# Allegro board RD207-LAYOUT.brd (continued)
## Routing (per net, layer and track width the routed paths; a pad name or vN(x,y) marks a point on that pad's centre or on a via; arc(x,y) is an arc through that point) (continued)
GND: length 396.6
  TOP w0.25: CN9.5 426.72,126.75 ; 426.72,126.75 427.32,126.15 427.63,125.83 ; 426.72,126.75 426.22,127.25 CN9.7 ; CN9.24 v1(415,131.25) ; CN9.32 419.8,133.25 419.33,133.72 v1(419.2,134.3) 419.2,134.95 419.5,135.25 CN9.40 ; v1(414.5,129.35) 415.25,129.35 416.15,130.25 CN9.20 ; v1(413.8,125.2) 414.66,125.46 417.45,128.25 CN9.12 ; CN9.39 426.75,135.25 v1(427.5,134.5) 426.25,133.25 CN9.31 ; v1(429.5,125.7) 426.95,128.25 CN9.11 ; CN9.50 419.5,137.75 419.33,137.92 v1(419.2,138.5) ; CN9.8 418.85,127.25 v1(418.2,126.6) 419.1,126.75 CN9.6 ; CN9.16 416.75,129.25 414.85,127.35 v1(413.8,127.35) ; v1(429.4,131.7) 428.95,131.25 CN9.23 ; v1(429.6,127.8) 429.09,128.11 427.95,129.25 CN9.15 ; CN9.19 429.1,130.25 v1(429.55,129.8)
  TOP w0.3: 175.5,72.25 178,72.25 ; 405.2,205.56 405.2,205.05 405.5,204.75 405.5,203.25 ; 186.5,74.29 186.5,75.76 ; 127.3,73 126.75,73 126.5,73.25 v1(126.5,75.25) 127,75.75 128.08,75.75 ; 81,88 81,86.75 80.75,86.5 IC32.2 ; 410.86,105.5 v1(409.6,105.5) ; 427.63,125.83 427.63,125.1 ; v1(409.45,147.78) 409.19,147.24 409.07,147.12 IC14.8 ; v1(409.45,147.78) IC14.9 ; v1(409.45,147.78) 408.71,148.51 408.1,148.51 ; 184,79.75 183.75,79.5 183.75,78.25 184,78 184,77 183.75,76.75 IC35.2 181.32,76.75 ; IC15.7 406.52,87.75 ; 141.7,83.5 142.25,83.5 142.5,83.25 142.5,81.75 141.75,81 140.49,81 ; 397.5,204.2 398.81,204.2 ; IC33.2 125.75,79.5 v1(125.25,80) ; 404.49,86 404.49,87.5 ; v1(399.55,142.7) 400.07,143.22 IC14.19 ; C121.2 88.55,81.95 88.5,82 88.5,82.5 ; 412.25,82.75 412.25,81.49 ; v1(130.5,83.5) 130.5,84.76 ; IC15.19 409.77,77.5 ; 403.1,140 402.24,140 ; 120.95,74 121.75,74 v1(122.5,73.25) ; 417.85,105.5 416.99,105.5 ; 83.5,85.51 v1(83.5,84.25) ; v1(128,88.25) 128,86 127.75,85.75 IC34.2 ; 405.5,203.25 408,203.25 ; 405.5,203.25 404.55,203.25 ; 404.3,208.25 404.7,208.25 405.2,207.75 405.2,205.94 ; IC15.6 407.18,87.25 ; 89.95,76.75 90.75,76.75 91.5,76 v1(91.5,74) 89.74,74 ; C126.2 v1(406.25,212.25) ; 186.64,97 187.5,97 ; C123.2 135.5,80.3 v1(135.5,79) ; C129.2 418.7,205.45 419.5,206.25 419.5,207 419,207.5 418.55,207.5 ; 109.7,70 110.5,70 v1(111.25,69.25) ; v1(141,79) 141,80.3 C124.2 ; 418.51,205 v1(417.25,205) ; 400.5,204.01 v1(400.5,202.75) ; 99.3,92.95 99.3,93.81 ; 168.4,75.8 169.55,75.8 v1(170,76.25) ; 419.5,202.5 422.19,202.5 ; 419.5,202.5 419.5,203.45 418.7,204.25 418.7,204.81 ; 419.5,202.5 418.55,202.5 ; v1(122.5,71) 120.49,71 ; 402.05,138.95 402.05,139.81 ; 110.75,67.25 109.24,67.25 ; 413.75,81.3 412.44,81.3 ; 410.75,81.3 412.06,81.3 ; 436.69,216.05 437.43,216.05 C114.2 ; 411.72,204.2 412.81,204.2 ; 410.51,85.99 410.51,86.75 ; 183.75,87 183.75,84.75 184,84.5 184,83.25 183.75,83 IC36.2 ; v1(416.25,211) 417.25,212 C107.2 ; 65.35,62 64.49,62 ; IC15.3 409.12,86.5 408.38,87.25 ; 130.5,78.51 v1(130.5,77.25) ; v1(137.5,82.25) 137.5,83 137,83.5 136.2,83.5 ; v1(90,81) 88.74,81 ; 64.3,63.05 64.3,62.19 ; 416.8,106.55 416.8,105.69 ; 105,74.24 v1(105,75.75) ; IC15.9 405.23,87.5 ; 78.9,68.8 77.69,68.8 ; 186.5,80.75 186.5,82.01 ; 81.64,97 83,97 ; IC15.8 405.88,87.38 ; 111.25,73.26 v1(111.25,71.75) ; 399.19,204.2 400.31,204.2 ; 427.3,126.13 426.71,126.72 ; 78.5,81 79.25,81 ; 79.25,81 79,80.75 ; 79.25,81 IC31.2 ; 83.5,80.01 v1(83.5,78.75) ; 89.45,83.5 88.3,83.5 ; 414.5,204.01 v1(414.5,202.75) ; v1(96.5,81) 95.24,81 ; 420.95,211.25 420.95,210.15 ; 405.01,205.75 v1(403.75,205.75) ; 414.31,204.2 413.19,204.2 ; 413,202.5 413,204.01 ; 165.5,76.45 v1(165.5,78) ; 419.5,212.2 418.02,212.2 ; 414.2,115.5 414.2,114.19 ; 410.69,85.4 411.75,85.4 ; 106.8,74.25 105.95,74.25 105.75,74.05 105.19,74.05 ; IC15.5 407.82,87.5 ; 151.5,97.64 151.5,98.51 ; 100.35,94 99.49,94 ; 107.3,74.25 108.75,74.25 ; 77.5,70.25 77.5,68.99 ; 404.31,85.4 403.25,85.4 ; 130.64,97 131.55,97 ; 399,202.75 399,204.01 ; IC15.4 408.48,87.25
  TOP w0.4: 401.31,211.86 v1(401.31,210.5) ; 417.6,107.5 417.5,107.5 ; 417.5,107.5 D10.A ; 417.5,107.5 418,107
  TOP w0.45: C52.2 410.86,105.5 ; C39.2 186.64,97 ; C97.2 151.5,97.64 ; C35.2 130.64,97 ; C25.2 81.64,97
  TOP w0.5: 410.93,103.5 v1(409.6,103.5) ; 404.31,85.4 IC15.10 404.49,86 ; 409.25,142 408.76,142.49 IC14.1 ; 418.55,207.5 IC23.2 ; IC21.2 404.3,208.25 ; 76.12,73.27 77.55,73.27 ; 149.43,94.5 148.29,94.5 ; 411.2,103.22 411.2,102.2 411,102 411,100.78 ; 181.09,101.9 181.09,99.06 180.59,98.56 ; IC28.2 89.95,76.75 ; 406,216.5 L17.2 L17.1 410,216.5 ; 426.75,217.75 PS7.2 ; IC18.2 136.2,83.5 ; 410.51,85.99 IC15.1 410.69,85.4 ; 420.31,140.44 419.6,140.44 419.2,140.04 v1(419.2,138.5) ; 133,97.5 L15.2 L15.1 136.75,97.5 ; 425.88,140.44 426.8,140.44 ; 187.42,94 188.5,94 ; 393.75,216.5 L16.1 L16.2 389.75,216.5 ; 131.32,94 133,94 ; IC2.2 410.6,111.25 ; 127.3,73 IC20.2 ; 75.65,73.48 75.65,74.65 ; 89.75,97.5 L14.1 L14.2 86,97.5 ; 81.58,94 82.5,94 ; IC30.2 165.5,76.45 ; IC22.2 404.55,203.25 ; IC19.2 141.7,83.5 ; 149.43,92.5 148.29,92.5 ; 146.57,94 147.71,94 ; 413.93,114 v1(412.7,114) ; 107.3,74.25 IC1.2 106.8,74.25 ; IC17.2 97.67,83.5 ; IC10.2 109.7,70 ; IC14.10 408.1,148.51 ; IC16.2 89.45,83.5 ; IC29.2 120.95,74 ; IC24.2 418.55,202.5
  TOP w0.6: CN9.60 420.31,140.44 ; CN9.59 425.88,140.44 ; CT2.5 124.59,97.91 ; 435,216.29 v1(435,217.5) ; 436.5,216.29 v1(436.5,217.5) ; CT1.5 75.59,96 ; CT3.5 181.09,101.9
  TOP w0.8: 418.51,205 C129.2 418.7,204.81 ; 436.69,216.05 C115.2 436.5,216.29 ; C143.2 83.5,80.01 ; 414.5,204.01 R124.2 414.31,204.2 ; C98.2 149.43,94.5 ; C38.2 187.42,94 ; 99.3,93.81 C85.2 99.49,94 ; 413.93,114 C48.2 414.2,114.19 ; C99.2 149.43,92.5 ; C50.2 111.25,73.26 ; C144.2 83.5,85.51 ; 105,74.24 C51.2 105.19,74.05 ; 400.5,204.01 C105.2 400.31,204.2 ; C125.2 128.08,75.75 ; 420.95,210.15 C128.2 ; 402.24,140 C117.2 402.05,139.81 ; 398.81,204.2 R115.1 ; R115.1 399.19,204.2 ; R115.1 399,204.01 ; C146.2 130.5,78.51 ; C127.2 405.2,205.56 ; C127.2 405.2,205.94 ; C127.2 405.01,205.75 ; C101.2 401.31,211.86 ; 413,204.01 C108.1 ; C108.1 413.19,204.2 ; C108.1 412.81,204.2 ; 140.49,81 C124.2 ; C24.2 81.58,94 ; 411.2,103.22 R24.1 410.93,103.5 ; 130.5,84.76 C147.2 ; 64.49,62 LED2.C 64.3,62.19 ; 418.02,212.2 C107.2 ; 416.8,105.69 C53.2 416.99,105.5 ; 77.5,68.99 R142.1 77.69,68.8 ; 412.25,81.49 C118.2 ; C118.2 412.06,81.3 ; C118.2 412.44,81.3 ; 75.65,73.48 PC7.3 76.12,73.27 ; C116.2 435,216.29 ; 95.24,81 C122.2 ; 109.24,67.25 C93.2 ; 186.5,82.01 C150.2 ; C37.2 131.32,94 ; C89.2 146.57,94 ; 120.49,71 C141.2 ; 186.5,75.76 C149.2 ; C140.2 89.74,74 ; C142.2 168.4,75.8 ; 88.74,81 C121.2
  TOP w1: PS6.2 152.75,98.72 151.5,98.72 ; 66.7,65 TP9.1 62.3,65 ; 148,94.5 148,97.75 148.97,98.72 151.5,98.72 ; 148,94.5 148.29,94.5 ; 148,94.5 148,94 ; 62.9,57.83 62.9,56.75 ; 439,217.5 v1(436.5,217.5) v1(435,217.5) 430.75,217.5 430.29,217.97 PS7.2 ; 151.5,98.51 151.5,98.72 ; 147.71,94 148,94 ; 148,94 148,92.5 ; 148,92.5 148.29,92.5 ; 148,92.5 148,87.06 ; CN8.2 411,100.78 ; 63.42,59 64.5,59
  TOP w1.2: C120.2 57.65,48 ; C120.2 59.25,50.75 ; C120.2 57.65,53.25 ; 62.9,42.9 PS2.7 62.9,46.1 ; 63.42,59 C23.2 62.9,57.83
  TOP w1.5: TP54.1 423.5,214.9 ; TP54.1 425.95,217 ; TP54.1 421.05,217 ; CN8.2 411,97.1
  TOP w1.7: TP52.1 148,87.06
  CONDUCTIVE2 w0.3: PS2.7 61.8,43.4 ; PS2.7 64,43.4 ; PS2.7 61.85,45.55 ; PS2.7 64,45.6 ; 153.25,98 PS6.2 155.75,97.93
  CONDUCTIVE2 w0.5: PS7.2 428.46,216.5 ; PS7.2 430.25,217.97 ; PS7.2 426.75,217.97
  BOTTOM w0.3: 431.45,129.85 430.3,129.85
  BOTTOM w1: 62.9,46.05 PS2.7 62.9,42.85
  vias: v1(15.5,24) v1(15.5,17) v1(28.5,24) v1(30.5,11) v1(40.5,24) v1(40.5,9) v1(52.5,11) v1(54.5,24) v1(58.5,30) v1(58.5,26) v1(58.5,9) v1(60.5,52) v1(60.5,49) v1(60.5,19) v1(63,56.5) v1(63.5,40) v1(63.5,31) v1(65,59) v1(66,52) v1(66.5,9) v1(69.5,63) v1(70.5,46) v1(70.5,35) v1(71.5,52) v1(72.5,12) v1(73.5,65.5) v1(73.5,61) v1(74.5,91) v1(74.5,86) v1(74.5,80) v1(75,54) v1(76.5,76.75) v1(77.5,73.25) v1(78.25,79) v1(78.5,46) v1(78.5,9) v1(79.25,60.25) v1(79.5,67) v1(79.7,55.73) v1(81,88.75) v1(83.5,19) v1(84,51.25) v1(85,69.5) v1(85.5,34) v1(86.25,53.5) v1(86.5,49) v1(86.5,9) v1(87.75,79.25) v1(89,66) v1(89.5,61.01) v1(91.5,50) v1(94.5,9) v1(95.5,54) v1(96.5,70) v1(96.5,66) v1(96.5,61) v1(97.5,76.25) v1(98.5,72.75) v1(98.75,44) v1(99.5,91) v1(99.5,30) v1(100.5,89) v1(101.5,85.5) v1(101.5,81) v1(102.5,54) v1(102.5,19) v1(102.5,9) v1(104.75,78.5) v1(105,69.5) v1(106.5,63) v1(106.75,65.75) v1(108.5,54) v1(108.5,9) v1(110.75,50) v1(111.5,78.5) v1(111.5,63) v1(114,55.75) v1(114.5,9) v1(114.75,51.25) v1(115.5,28) v1(116,59.75) v1(117,66.75) v1(117.25,43.75) v1(118.5,78.5) v1(118.5,19) v1(119,47.75) v1(121.5,9) v1(122.25,88) v1(122.25,84.75) v1(122.25,53.25) v1(122.75,42.75) v1(123,13.25) v1(123.25,66.75) v1(123.25,60.75) v1(123.25,38) v1(125.25,83.5) v1(126.5,69) v1(126.5,60.75) v1(126.5,53) v1(126.5,49) v1(127,43) v1(128.5,37.25) v1(128.5,32.5) v1(131.5,69) v1(131.75,88.25) v1(132.5,61) v1(132.5,53) v1(132.5,25) v1(132.75,37.25) v1(133,17.25) v1(133.25,41.75) v1(134.75,75.25) v1(137.25,70) v1(138.5,61) v1(138.5,53) v1(139.25,49) v1(139.75,75.25) v1(140.75,25) v1(141.95,38.5) v1(143.25,18.25) v1(144.25,25.75) v1(144.75,79) v1(145.5,74) v1(145.5,66.75) v1(145.5,61) v1(146.75,19) v1(147.5,81) v1(147.5,33) v1(148,53.25) v1(149.25,20.75) v1(149.5,16) v1(150.5,49) v1(150.5,42) v1(151.5,24) v1(152.25,81) v1(153.5,9) v1(154.5,66.75) v1(155.25,74) v1(155.25,61) v1(156.95,38.5) v1(157,81) v1(158.35,47) v1(158.75,53) v1(159.25,81) v1(162.5,66.75) v1(162.5,42) v1(162.5,32) v1(163,74.25) v1(163.5,61) v1(165.5,24) v1(167.5,9) v1(168.5,53) v1(169.5,67) v1(169.5,62) v1(169.5,49) v1(169.5,39) v1(170.5,15) v1(172.5,79) v1(173.5,75.5) v1(173.5,67) v1(176.25,70) v1(177.5,79) v1(177.5,77) v1(177.5,65.75) v1(177.5,51) v1(177.5,31) v1(177.75,59.25) v1(177.75,55.75) v1(178.5,40) v1(178.5,9) v1(179.5,92) v1(179.5,85.25) v1(180,75) v1(183.5,35) v1(184.25,65.75) v1(184.25,59.25) v1(184.5,53) v1(184.5,23) v1(184.75,90) v1(184.75,87.25) v1(184.75,80.5) v1(184.75,74.75) v1(184.75,70.75) v1(185.5,15) v1(189.5,29) v1(191.5,44) v1(193.5,9) v1(199.5,15) v1(200.5,37) v1(205.5,9) v1(208.5,29) v1(214.5,15) v1(219.5,9) v1(227.5,9) v1(235.5,15) v1(243.5,9) v1(253.5,15) v1(253.75,9) v1(277.75,9) v1(279.5,15) v1(286.5,9) v1(296.5,9) v1(306.5,9) v1(324.5,9) v1(339.5,10) v1(355.5,9) v1(369.5,10) v1(375.2,219.4) v1(375.5,207.5) v1(380.5,247) v1(384.5,186) v1(385.5,214) v1(385.5,117) v1(385.5,86) v1(385.5,81.75) v1(385.5,41) v1(385.5,26) v1(385.6,137.3) v1(386.5,66) v1(386.6,204.3) v1(387.5,161) v1(387.5,59) v1(389.25,217.25) v1(389.5,167) v1(389.5,48) v1(389.5,30) v1(390,145) v1(390,137.5) v1(390.5,198.75) v1(390.75,192.5) v1(391.25,177.25) v1(392.25,201.75) v1(393.7,214.5) v1(395.1,128.2) v1(396.25,163.5) v1(396.4,197) v1(396.4,176.7) v1(396.5,160.1) v1(397.5,137.5) v1(401.5,130.25) v1(402.25,155) v1(402.25,150.75) v1(402.25,134.25) v1(402.5,198) v1(402.5,187) v1(402.5,10) v1(404,138) v1(405.5,131.5) v1(405.75,134.25) v1(405.75,115.25) v1(405.95,216.7) v1(405.9,98.2) v1(406.5,88) v1(406.5,70) v1(406.5,46) v1(406.5,33) v1(408.75,101.25) v1(409.5,18) v1(409.75,163.5) v1(409.75,154) v1(409.75,134.25) v1(410,201.75) v1(410.15,140.9) v1(410.25,184) v1(410.5,168) v1(410.6,111) v1(411.5,60) v1(412.25,132.25) v1(412.5,187.5) v1(412.5,85) v1(412.75,152.25) v1(414,138.25) v1(415,134.5) v1(415.25,101.25) v1(415.5,45) v1(416.25,188.25) v1(416.25,155.5) v1(416.25,153) v1(420,147) v1(421,164) v1(421.25,144) v1(421.5,106) v1(422.5,85) v1(422.5,10) v1(425.25,152.5) v1(426.5,54) v1(426.5,27) v1(426.75,141.25) v1(428.25,155) v1(430,198) v1(430,145.5) v1(430,115) v1(433,10) v1(433.5,139.25) v1(433.75,149) v1(435.5,18) v1(438.5,112) v1(438.5,86) v1(438.5,45) v1(440,216) v1(440,198) v1(440,186) v1(440,167) v1(440,142) v1(440,117) v1(440,99) v1(440,81) v1(440,59) v1(440,33) v1(440,18) v1(441.25,162.25) v1(441.25,155) v1(441.5,212)
GND_5VAC: length 75.4
  TOP w0.3: 151.5,108.86 151.5,107.46
  TOP w0.45: C96.2 151.5,108.86
  TOP w0.5: 136.69,108.63 136.69,111.03 ; 151.5,107.46 151.5,107.25 ; 149.43,114.25 148.34,114.25 ; TP37.1 145.75,112.91 ; 145.75,112.91 144.59,112.91 ; 145.75,112.91 147.78,112.91 ; 149.43,112.75 148,112.75 ; R84.2 90.5,110.6 89.69,109.79 89.69,108.63 ; 149.49,115.86 148.36,115.86 ; v1(89,111.2) 90.22,111.2
  TOP w0.6: R99.2 v1(137.9,111.31) ; 97.82,112.8 v1(99,112.8)
  TOP w0.8: C94.2 149.43,114.25 ; R144.1 149.49,115.86 ; C88.2 144.59,112.91 ; 136.69,111.03 R99.2 ; 90.22,111.2 R84.2 ; C84.2 97.82,112.8 ; C95.2 149.43,112.75
  TOP w1: 151.5,107.25 151.25,107.25 148.75,109.75 v1(148.75,110.75) 148.07,111.43 148.07,112.91 ; PS6.5 153.58,107.21 153.5,107.25 151.75,107.25 ; v1(149.25,118.25) 148.07,117.07 148.07,115.86 ; 148.07,115.86 148.07,114.25 ; 148.07,115.86 148.36,115.86 ; 148.07,112.91 148.07,114.25 ; 148.07,112.91 147.78,112.91 ; 148.07,114.25 148.34,114.25
  TOP w1.5: IC9.4 136.69,108.63 ; 89.69,108.63 IC8.4
  CONDUCTIVE2 w1: 137.25,107.5 119.75,107.5 119.5,107.25 103.75,107.25
  CONDUCTIVE3 w0.3: 153.3,108 PS6.5 155.5,107.87
GND_5VDC: length 23.9
  TOP w0.3: 423.61,231 422.5,231 ; 410.19,227.55 410.19,230.12 ; 393.69,230.12 393.69,227.55
  TOP w0.45: C113.2 423.61,231
  TOP w0.5: 423.18,234.25 422.25,234.25 ; 423.18,232.5 422.25,232.5 ; 423.18,236 422.25,236 ; 409.92,230.31 v1(408.6,230.31) ; 393.42,230.31 v1(392.1,230.31) ; 418.08,231.91 v1(419.5,231.91) ; 401.57,231.91 v1(402.8,231.91)
  TOP w0.6: 427.25,226.8 PS7.5 429.75,226.87
  TOP w0.8: C103.2 401.57,231.91 ; C112.2 423.18,232.5 ; C111.2 423.18,234.25 ; 410.19,230.12 R129.2 409.92,230.31 ; R145.1 423.18,236 ; 393.42,230.31 R114.2 393.69,230.12 ; C106.2 418.08,231.91
  TOP w1.5: 393.69,227.55 IC12.4 ; IC13.4 410.19,227.55
  CONDUCTIVE2 w0.5: 427.3,226.75 PS7.5 429.5,226.62
  vias: v1(421.75,235.25) v1(421.75,233.5) v1(421.75,231.75) v1(422.25,226.25) v1(424,226.25) v1(425.75,226.25)
GND_24V: length 154.6
  TOP w0.3: 39.7,71.05 39.7,70.19 ; 38.65,70 39.51,70 ; 34.3,71.05 34.3,70.19 ; 39.7,68.95 39.7,69.81 ; 36.3,37 36.3,35.69 ; 36.3,34.45 36.3,35.31 ; 34.3,68.9 34.3,69.81 ; 38,35.5 36.49,35.5 ; 35.35,70 34.49,70
  TOP w0.4: 68.27,76.8 67.01,76.8 Q7.S ; 68.73,76.8 v1(70,76.8)
  TOP w0.5: PS2.1 45.85,44.5 ; PS2.1 47.6,46.1 ; PS2.1 47.6,42.8 ; 62.42,83 v1(60.83,83) ; 111.42,84 v1(109.5,84) ; 168.43,84 v1(166.5,84)
  TOP w0.6: CN1.2 34.5,65 ; CN1.2 34.5,62 ; CN1.2 36,63.5
  TOP w0.8: 68.27,76.8 R143.1 68.73,76.8 ; 36.3,35.69 LED1.C ; LED1.C 36.49,35.5 ; LED1.C 36.3,35.31 ; 34.3,70.19 C19.2 ; C19.2 34.3,69.81 ; C19.2 34.49,70 ; 39.7,69.81 R12.2 ; R12.2 39.7,70.19 ; R12.2 39.51,70 ; C12.2 168.43,84 ; C1.2 62.42,83 ; C8.2 111.42,84
  TOP w1: C22.2 40.1,37.75 ; C22.2 40.1,33.25 ; C22.2 38.5,35.5 ; TP8.1 47.5,55.15 ; TP8.1 49.7,57 ; TP8.1 45.3,57 ; TP8.1 47.5,58.85 ; TP5.1 38.8,63 ; TP5.1 43.2,63 ; TP5.1 41,61.15 ; TP5.1 41,64.85 ; C21.2 38.75,32.9 ; C21.2 36.5,34 ; C21.2 34.5,32.9
  TOP w1.2: v1(375.6,108.3) C70.2 375.6,114.4 374.31,115.69 PS4.2 ; PS5.2 374.31,35.19 375.6,33.9 C78.2 v1(375.6,27.6) ; v1(375.6,186.6) C62.2 375.6,193.4 374.31,194.69 PS3.2 ; C120.1 53.35,53.75 ; C120.1 53.35,47.75 ; C120.1 51.5,50.75
  TOP w1.5: C20.2 43.05,50.75 ; ZD1.A v1(37.8,39.5) ; ZD1.A 35.55,42 ; ZD1.A 35.55,37.5 ; 40.75,53.75 40.75,47.5
  CONDUCTIVE2 w0.3: PS2.1 46.6,45.5 ; PS2.1 48.6,43.5 ; PS2.1 48.6,45.5 ; PS2.1 46.55,43.45 ; CN1.2 33.5,62.5 ; CN1.2 35.5,62.5 ; CN1.2 35.5,64.5 ; CN1.2 33.5,64.5
  CONDUCTIVE3 w0.3: PS2.1 48.7,45.6 ; PS2.1 48.55,43.55 ; PS2.1 46.5,43.4 ; PS2.1 46.5,45.6 ; CN1.2 33.5,62.5 ; CN1.2 35.5,64.5 ; CN1.2 33.5,64.5 ; CN1.2 35.5,62.5
  CONDUCTIVE3 w0.5: PS4.2 374.31,118.11 374.7,118.5 ; PS4.2 374.31,115.89 374.7,115.5 ; PS4.2 375.75,117 ; 374.7,194.5 374.31,194.89 PS3.2 ; PS5.2 374.31,37.61 374.6,37.9 ; PS5.2 375.75,36.5 ; PS5.2 374.31,35.39 374.6,35.1 ; PS3.2 374.31,197.11 374.7,197.5 ; PS3.2 375.75,196
  BOTTOM w1: PS2.1 47.6,46.55 ; PS2.1 47.6,42.45 ; PS2.1 45.55,44.5
  vias: v1(38,42) v1(38,36.5) v1(38.4,34.4) v1(39,43.5) v1(39,40.5) v1(39,38) v1(44.5,57)
/DO1_BI: length 70.1
  TOP w0.25: CN9.42 419.55,135.75 v1(419.15,136.15)
  TOP w0.3: R138.1 404,93.45 v1(404,136) ; IC15.2 409.77,86.67 409.7,86.75 409.7,87.56
  TOP w0.8: 409.7,87.56 R138.1
  BOTTOM w0.3: v1(404,136) 418,136 v1(419.15,136.15)
/MAINRLY_24V: length 62.1
  TOP w0.5: 62.35,85.28 62.35,89.2 RLY1.8 ; 59.5,84.65 59.5,82.47 R139.1 ; RLY2.8 108.75,87.25 110,86 111.16,86 ; 62.08,85 59.85,85 ; 168.07,86 167.25,86 165.75,87.5 RLY3.8 ; 64.2,76 63,76 59.4,79.6 59.4,81.47
  TOP w0.8: 168.07,86 D3.A ; 64.2,76 Q7.D ; 62.08,85 D1.A 62.35,85.28 ; R139.1 59.4,81.47 ; D2.A 111.16,86
  TOP w1.7: 59.85,85 TP50.1 59.5,84.65
  BOTTOM w1.5: RLY2.8 108.75,92.75 ; RLY2.8 110.75,94.8 ; RLY2.8 106.75,94.8 ; RLY1.8 59.75,89.5 ; RLY1.8 59.75,94 ; RLY1.8 57.75,91.8 ; RLY1.8 62,91.8 ; RLY3.8 163.45,91.8 ; RLY3.8 165.75,90 ; RLY3.8 165.75,94.1
/PWM1A_BI: length 37.2
  TOP w0.25: 428.5,132.2 428.05,131.75 CN9.25
  TOP w0.3: v1(430.3,139.5) 430.3,134 428.5,132.2 ; 412.76,141 v1(411.55,141) 409.32,143.22 IC14.2
  TOP w0.8: 412.76,141 R132.1
  BOTTOM w0.3: v1(430.3,139.5) 413.05,139.5 v1(411.55,141)
/PWM1B_BI: length 24
  TOP w0.25: CN9.26 418.45,131.75 418.4,131.8
  TOP w0.3: 418.4,131.8 416.6,133.6 v1(416.6,141) ; IC14.3 410.18,143.88 v1(411.55,142.5) 412.76,142.5
  TOP w0.8: 412.76,142.5 R133.1
  BOTTOM w0.3: v1(411.55,142.5) 413.05,141 v1(416.6,141)
/PWM2A_BI: length 37.7
  TOP w0.25: CN9.27 427.65,132.25 427.98,132.57
  TOP w0.3: 427.98,132.57 429.6,134.2 429.6,138.6 429.3,138.9 v1(429.3,142.6) ; IC14.4 411.02,144.53 v1(411.55,144) 412.76,144
  TOP w0.8: 412.76,144 R134.1
  BOTTOM w0.3: v1(429.3,142.6) 412.95,142.6 v1(411.55,144)
/PWM2B_BI: length 25.7
  TOP w0.25: 417.6,133.6 418.95,132.25 CN9.28
  TOP w0.3: IC14.5 410.89,145.18 410.99,145.27 v1(411.55,145.5) 412.76,145.5 ; v1(416.6,143.9) 417.6,142.9 417.6,133.6
  TOP w0.8: 412.76,145.5 R135.1
  BOTTOM w0.3: v1(416.6,143.9) 413.15,143.9 v1(411.55,145.5)
/PWM3A_BI: length 38.8
  TOP w0.25: CN9.29 427.25,132.75 427.75,133.25
  TOP w0.3: 427.75,133.25 428.9,134.4 428.9,138.4 428,139.3 v1(428,145.5) ; 412.76,147 v1(411.55,147) 410.38,145.82 IC14.6
  TOP w0.8: 412.76,147 R136.1
  BOTTOM w0.3: v1(428,145.5) 413.05,145.5 v1(411.55,147)
/PWM3B_BI: length 29.6
  TOP w0.25: CN9.30 419.35,132.75 418.2,133.9
  TOP w0.3: 418.2,133.9 418.2,146.41 v1(418.1,147) ; 412.76,148.5 v1(411.55,148.5) 409.52,146.47 IC14.7
  TOP w0.8: 412.76,148.5 R137.1
  BOTTOM w0.3: v1(418.1,147) 413.05,147 v1(411.55,148.5)
/PWM_U_A: length 122.3
  TOP w0.3: 395.77,142 397.25,142 399.12,143.88 IC14.18 ; TP44.1 393.5,144 393.5,193.09 393.43,193.46 393.21,193.79 389,198 389,215 379.5,224.5 379.5,246.3 379,246.8 378.19,246.8
  TOP w0.5: 377.73,246.8 377,246.8 376.53,247.27 376.12,247.27
  TOP w0.6: PC1.3 376.12,247.27
  TOP w0.8: 377.73,246.8 R35.2 378.19,246.8
  TOP w1.7: 395.77,142 TP44.1
/PWM_U_B: length 99.8
  TOP w0.3: IC14.17 398.23,144.53 v1(397.75,145) 395.77,145 ; v1(392.4,145) 392.7,145.52 392.7,193.3 388.49,197.51 388.27,197.84 388.2,198.21 388.2,214.7 379.6,223.3 378.19,223.3
  TOP w0.5: 376.12,223.77 376.7,223.77 377.17,223.3 377.73,223.3
  TOP w0.6: PC2.3 376.12,223.77
  TOP w0.8: 377.73,223.3 R40.2 378.19,223.3
  TOP w1.7: TP45.1 395.77,145
  BOTTOM w0.3: v1(397.75,145) v1(392.4,145)
/PWM_V_A: length 47.3
  TOP w0.3: IC14.16 399.32,145.18 397.75,146.75 v1(397.75,148) 395.77,148 ; 379.69,165.3 389.5,165.3 390.6,164.2 v1(390.6,148)
  TOP w0.5: PC3.3 378.2,165.77 378.67,165.3 379.23,165.3
  TOP w0.8: 379.69,165.3 R48.2 379.23,165.3
  TOP w1.7: TP46.1 395.77,148
  BOTTOM w0.3: v1(397.75,148) v1(390.6,148)
/PWM_V_B: length 41.8
  TOP w0.3: v1(385,151) 385,142 384.3,141.3 379.69,141.3 ; 395.77,151 v1(397.75,151) 398.85,149.9 398.85,147 400.02,145.82 IC14.15
  TOP w0.5: 379.23,141.3 377.97,141.3 377.5,141.77 376.12,141.77
  TOP w0.6: PC4.3 376.12,141.77
  TOP w0.8: 379.69,141.3 R53.2 379.23,141.3
  TOP w1.7: TP47.1 395.77,151
  BOTTOM w0.3: v1(397.75,151) v1(385,151)
/PWM_W_A: length 104.9
  TOP w0.3: v1(386.6,154) 387,152.87 387,84.8 385.5,83.3 379.69,83.3 ; 395.77,154 v1(397.75,154) 399.6,152.15 399.6,147.3 400.43,146.47 IC14.14
  TOP w0.5: 379.35,83.3 378.87,83.3 378.4,83.77 PC5.3
  TOP w0.8: 379.35,83.3 R61.2 379.69,83.3
  TOP w1.7: 395.77,154 TP48.1
  BOTTOM w0.3: v1(397.75,154) v1(386.6,154)
/PWM_W_B: length 131.5
  TOP w0.3: IC14.13 400.82,147.12 400.45,147.5 400.45,154.3 v1(397.75,157) 395.77,157 ; v1(388.6,157) 388.6,64.4 383.5,59.3 379.69,59.3
  TOP w0.5: R66.2 379.03,59.77 376.12,59.77
  TOP w0.6: PC6.3 376.12,59.77
  TOP w0.8: R66.2 379.69,59.3
  TOP w1.7: TP49.1 395.77,157
  BOTTOM w0.3: v1(397.75,157) v1(388.6,157)
AC_L_IN_W: length 107.4
  TOP w1: RLY3.5 163.75,116.8 ; RLY3.5 167.75,116.8 ; RLY3.5 165.75,118.75 ; 171.25,116.8 RLY3.4 173.25,118.75 ; R9.2 168.5,127 ; R9.2 173.5,127 ; R9.2 171,129.5 ; R9.2 171,124.5
  CONDUCTIVE2 w1: RLY3.5 165.75,118.75 ; RLY3.5 167.75,116.8 ; RLY3.5 163.75,116.8 ; R9.2 171,129.25 ; R9.2 171,124.75 ; R9.2 173.25,127 ; R9.2 168.5,127 ; 171.25,116.8 RLY3.4 173.25,118.75
  CONDUCTIVE3 w1: 173.25,118.75 RLY3.4 171.25,116.8 ; R9.2 173.5,127 ; R9.2 171,129.5 ; R9.2 168.5,127 ; R9.2 171,124.5 ; RLY3.5 163.75,116.8 ; RLY3.5 165.75,118.75 ; RLY3.5 167.75,116.8
  CONDUCTIVE3 w1.5: 143.51,260.47 L2.6 ; L2.6 140.18,262.89 ; L2.6 140.18,257.18 ; PS1.3 11.5,137.7 ; PS1.3 13.8,140 ; PS1.3 11.5,142.3 ; PS1.3 9.2,140
  BOTTOM w1: RLY3.5 163.75,116.8 ; RLY3.5 165.75,119 ; RLY3.5 168,116.8 ; 171.25,116.8 RLY3.4 173.25,119
  BOTTOM w1.5: R9.2 171,124.5 ; R9.2 171,129.5 ; R9.2 173.5,127 ; R9.2 168.5,127 ; 140.18,257.97 L2.6 ; L2.6 140.18,262.5 ; L2.6 142.68,260.47 ; L2.6 137.68,260.47
AC_N_IN: length 106.9
  TOP w1: R6.2 113.25,128.5 ; R6.2 108.25,128.5 ; R6.2 110.75,131 ; R6.2 110.75,126 ; 114.25,119.8 RLY2.4 116.25,122 ; L2.4 177.42,247.73 ; L2.4 175.17,245.48 ; L2.4 175.17,249.98 ; RLY2.5 108.75,121.75 ; RLY2.5 106.75,119.8 ; RLY2.5 110.75,119.8
  CONDUCTIVE2 w1: R6.2 110.75,131 ; R6.2 108.25,128.5 ; R6.2 110.75,126 ; R6.2 113,128.5 ; 114.25,119.8 RLY2.4 116.25,121.75 ; RLY2.5 106.75,119.8 ; RLY2.5 108.75,121.75 ; RLY2.5 110.75,119.8
  CONDUCTIVE2 w1.5: L2.4 175.17,250.13 ; L2.4 177.57,247.73 ; L2.4 175.17,245.33
  CONDUCTIVE3 w1: RLY2.5 108.75,121.75 ; RLY2.5 110.75,119.8 ; RLY2.5 106.75,119.8 ; 110.75,126.5 R6.2 108.75,128.5 ; 116.25,121.75 RLY2.4 114.25,119.8
  CONDUCTIVE3 w1.5: PS1.2 33.8,140 ; PS1.2 31.5,142.3 ; PS1.2 31.5,137.7 ; PS1.2 29.2,140 ; L2.4 177.57,247.73 ; L2.4 175.17,245.33 ; L2.4 172.77,247.73 ; L2.4 175.17,250.13
  BOTTOM w1: R6.2 110.75,131 ; R6.2 110.75,126 ; R6.2 113.25,128.5 ; R6.2 108.25,128.5 ; RLY2.5 108.75,122 ; RLY2.5 106.75,119.8 ; RLY2.5 110.75,119.8 ; 116.25,122 RLY2.4 114.25,119.8
AC_U: length 166.9
  TOP w0.3: 76.5,135.25 90.51,135.25
  TOP w0.8: 90.51,135.25 R75.1
  TOP w1: R1.1 72.25,129.5 ; R1.1 72.25,124.5 ; R1.1 74.75,127 ; R1.1 69.75,127 ; RLY1.6 59.75,109.75 ; RLY1.6 57.75,111.8 ; RLY1.6 61.75,111.8 ; RLY1.3 67.25,109.75 ; RLY1.3 69.25,111.8 ; RLY1.3 65.25,111.8 ; TP1.1 71.5,138 ; TP1.1 71.5,142 ; TP1.1 73.75,140 ; TP1.1 69.25,140
  TOP w1.5: C7.1 140.75,190.25 ; C7.1 138.5,188 ; C7.1 143,188 ; C7.1 140.75,185.75 ; C6.1 93.75,151.75 ; C6.1 96,154 ; C6.1 93.75,156.25 ; C6.1 91.5,154
  CONDUCTIVE2 w1: RLY1.3 69.25,111.8 ; RLY1.3 65.25,111.8 ; RLY1.3 67.25,109.75 ; R1.1 72.25,129.5 ; R1.1 74.75,127 ; R1.1 72.25,124.5 ; R1.1 69.75,127 ; RLY1.6 57.75,111.8 ; RLY1.6 61.75,111.8 ; RLY1.6 59.75,109.75
  CONDUCTIVE2 w1.5: C7.1 140.75,190.15 ; C7.1 140.75,185.85 ; C7.1 138.6,188 ; C7.1 142.9,188 ; C6.1 91.6,154 ; C6.1 93.75,156.15 ; C6.1 95.9,154 ; C6.1 93.75,151.85
  CONDUCTIVE3 w1: RLY1.6 59.75,109.75 ; RLY1.6 61.75,111.8 ; RLY1.6 57.75,111.8 ; C6.1 91.85,154 ; C6.1 93.75,155.9 ; C6.1 93.75,152.1 ; C6.1 95.65,154 ; R1.1 69.75,127 ; R1.1 74.75,127 ; R1.1 72.25,129.5 ; R1.1 72.25,124.5 ; RLY1.3 67.25,109.75 ; RLY1.3 69.25,111.8 ; RLY1.3 65.25,111.8
  CONDUCTIVE3 w1.5: C7.1 140.75,190.15 ; C7.1 138.6,188 ; C7.1 140.75,185.85 ; C7.1 142.9,188
  BOTTOM w1: R1.1 74.75,127 ; R1.1 72.25,124.5 ; R1.1 72.25,129.5 ; R1.1 69.75,127
  BOTTOM w1.5: C7.1 137.9,188 ; C7.1 143,188 ; C7.1 140.75,190.85 ; C7.1 140.75,185.15 ; 96.6,154 C6.1 93.75,151.15
  vias: v1(73,109.5) v1(73.5,113) v1(73.5,111) v1(74.5,114) v1(74.5,112) v1(74.5,109.5) v1(75.5,113) v1(75.5,111) v1(76,109.5)
AC_V: length 198.2
  TOP w0.3: 89.19,120.75 89.19,121.59 88.89,121.89 88.89,122.7 ; v1(89,127) 88.89,126 88.89,124.97 ; 137.69,119.53 137.69,121.4 138.68,122.39 139.7,122.39 ; 140.19,120.66 140.19,121.4 139.89,121.7 139.89,122.2 ; 88.89,124.7 88.89,123.08 ; v1(139.89,125.6) 139.89,124.08 ; v1(140.25,131) 140.25,133.25 138,135.5 136.52,135.5 ; 88.7,122.89 87.39,122.89 86.69,122.19 86.69,119.53 ; 139.89,122.58 139.89,123.7
  TOP w0.45: R101.1 137.69,119.53 ; R86.1 86.69,119.53
  TOP w0.6: L11.2 140.19,120.66 ; L10.2 89.19,120.75
  TOP w0.8: 88.89,122.7 C86.2 ; C86.2 88.89,123.08 ; C86.2 88.7,122.89 ; 139.89,124.08 R95.1 139.89,123.7 ; 139.7,122.39 C91.2 ; C91.2 139.89,122.2 ; C91.2 139.89,122.58 ; 88.89,124.97 R80.1 88.89,124.7
  TOP w1: RLY2.6 106.75,114.8 ; RLY2.6 108.75,112.75 ; RLY2.6 110.75,114.8 ; R6.1 120.25,126 ; R6.1 122.75,128.5 ; R6.1 120.25,131 ; R6.1 117.75,128.5 ; RLY2.3 114.25,114.8 ; RLY2.3 116.25,112.75 ; RLY2.3 118.25,114.8 ; TP2.1 131.25,140.5
  TOP w1.5: 133.5,154 C6.2 131.25,151.75 ; C9.1 138.5,154 ; C9.1 140.75,151.75 ; C9.1 143,154
  TOP w1.7: 136.52,135.5 TP2.1
  CONDUCTIVE2 w0.3: v1(139.89,125.6) 141.85,125.6 142.25,126 155.75,126 156,126.25 156,129 155.25,129.75 141.5,129.75 v1(140.25,131) ; v1(89,127) 95.25,127 95.5,127.25 95.5,135 95.25,135.25 91,135.25 90.25,134.5 v1(90.25,128.75)
  CONDUCTIVE2 w1: RLY2.6 110.75,114.8 ; RLY2.6 108.75,113 ; RLY2.6 106.75,114.8 ; RLY2.3 116.25,113 ; RLY2.3 118.25,114.8 ; RLY2.3 114.25,114.8
  CONDUCTIVE3 w0.3: 113,132.25 93.75,132.25 v1(90.25,128.75)
  BOTTOM w1: R6.1 122.75,128.5 ; R6.1 120.25,126 ; R6.1 117.75,128.5 ; R6.1 120.25,131
  BOTTOM w1.5: C9.1 140.75,151.15 ; C9.1 137.9,154 ; C9.1 143.6,154 ; C9.1 140.75,156.1 ; C6.2 134.1,154 ; C6.2 131.25,156.1 ; C6.2 131.25,151.15 ; C6.2 128.4,154
  vias: v1(121.25,116) v1(121.25,114) v1(122.25,117) v1(122.25,115) v1(123,131) v1(123,129) v1(123,127) v1(123.25,116) v1(123.25,114) v1(124,130) v1(124,128) v1(124,126) v1(124.25,117) v1(124.25,115) v1(125,131) v1(125,129) v1(125,127) v1(125.25,116) v1(125.25,114)
AC_W: length 132.6
  TOP w0.3: R87.1 161.95,135 177.5,135
  TOP w1: RLY3.6 163.5,111.8 ; RLY3.6 165.75,109.5 ; RLY3.6 168,111.8 ; RLY3.3 173.25,109.5 ; RLY3.3 175.5,111.8 ; RLY3.3 171,111.8 ; 188.44,116.5 185,116.5
  TOP w1.5: 180.5,188 C7.2 178.25,185.75 ; C9.2 176,154 ; C9.2 180.5,154 ; C9.2 178.25,156.25 ; C9.2 178.25,151.75 ; R9.1 180.5,129.5 ; R9.1 180.5,124.5 ; R9.1 178,127 ; R9.1 183,127
  TOP w1.7: TP3.1 188.44,116.5
  CONDUCTIVE2 w1: RLY3.3 171.5,111.8 ; RLY3.3 175,111.8 ; RLY3.3 173.25,110 ; RLY3.6 164,111.8 ; RLY3.6 165.75,110 ; RLY3.6 167.5,111.8
  CONDUCTIVE3 w1: RLY3.6 165.75,110 ; RLY3.6 164,111.8 ; RLY3.6 167.5,111.8 ; RLY3.3 175,111.8 ; RLY3.3 171.5,111.8 ; RLY3.3 173.25,110
  BOTTOM w1: RLY3.6 168,111.8 ; RLY3.6 163.5,111.8 ; RLY3.6 165.75,109.55 ; RLY3.3 173.25,109.5 ; RLY3.3 175.5,111.8 ; RLY3.3 171,111.8
  BOTTOM w1.5: C9.2 178.25,156.85 ; C9.2 181.1,154 ; C9.2 178.25,151.15 ; C9.2 175.4,154 ; C7.2 175.4,188 ; C7.2 178.25,190.85 ; C7.2 178.25,185.15 ; C7.2 181.1,188 ; R9.1 180.5,129.5 ; R9.1 180.5,124.5 ; R9.1 183,127 ; R9.1 178,127
  vias: v1(176.5,110.5) v1(177.5,111.5) v1(177.5,109.5) v1(178.5,110.5) v1(179.5,111.5) v1(179.5,109.5) v1(180.5,110.5) v1(181.5,111.5) v1(181.5,109.5) v1(187.5,128.5) v1(187.5,126.5) v1(187.5,124.5) v1(188.5,127.5) v1(188.5,125.5) v1(188.5,123.5) v1(189.5,128.5) v1(189.5,126.5) v1(189.5,124.5)
AD0: length 490.1
  TOP w0.25: CN9.9 426.6,127.75 428.5,125.85 v1(428.5,122.6)
  TOP w0.3: TP31.1 85.5,87 v1(85.5,84.45) 87.05,84.45 ; v1(399,122.5) 399,26.8 387.7,15.5 288,15.5 282,21.5 150.65,21.5 107.65,64.5 104.75,64.5 95.75,73.5 95.75,74.5 91.5,78.75 v1(91.5,82.55) 89.95,82.55
  TOP w0.5: IC16.4 87.05,84.45 ; IC16.1 89.95,82.55
  BOTTOM w0.3: v1(399,122.5) 427.5,122.5 v1(428.5,122.6) ; v1(85.5,84.45) 89.6,84.45 v1(91.5,82.55)
AD1: length 440.1
  TOP w0.25: v1(409.5,125) 410.5,124 414,124 417.75,127.75 CN9.10
  TOP w0.3: 133.8,84.45 134.3,84.45 134.75,84 134.75,82.8 135,82.55 135.7,82.55 ; v1(137.25,72) 137.25,79.75 135.95,81.05 135.95,82.38 ; 133.75,87.48 133.75,85.75 133.55,85.55 133.55,84.62 ; v1(391.5,125) 391.5,28.4 384.6,21.5 291,21.5 285,27.5 188.29,27.5 175.9,39.89 175.9,66.85 v1(173.5,69.25)
  TOP w0.5: 133.8,84.45 IC18.4 133.55,84.62 ; 135.95,82.38 IC18.1 135.7,82.55
  TOP w1.7: 133.75,87.48 TP34.1
  BOTTOM w0.3: v1(137.25,72) 140,69.25 v1(173.5,69.25) ; v1(409.5,125) v1(391.5,125)
AD2: length 130.7
  TOP w0.25: 430.2,126.8 429.15,126.8 427.2,128.75 CN9.13
  TOP w0.3: 406.45,207.45 406.45,207.75 405,209.2 404.3,209.2 ; TP38.1 402.5,210.25 v1(402.5,209.25) 403.25,209.2 403.8,209.2 ; v1(431.8,148.7) 431.8,127.9 430.7,126.8 430.2,126.8 ; v1(411.5,154) 412,154.5 412,184.5 393.8,202.7 v1(393.8,208.3)
  TOP w0.5: IC21.4 406.45,207.45 ; 404.3,209.2 IC21.1 403.8,209.2
  BOTTOM w0.3: v1(411.5,154) 426.5,154 v1(431.8,148.7) ; v1(402.5,209.25) 398.25,209.25 398,209.5 395,209.5 v1(393.8,208.3)
AD3: length 105.4
  TOP w0.25: 413.15,126.33 414.62,126.33 417.05,128.75 CN9.14
  TOP w0.3: 418.55,208.45 419.3,208.45 420.7,207.05 420.7,206.6 ; 418.05,208.45 417.3,208.45 v1(416.25,209.5) 417,210.25 418.48,210.25 ; 413.15,126.33 411.75,126.33 410.95,127.12 410.95,133.2 415.45,137.7 415.45,151.35 414.5,152.3 414.5,196.75 v1(416.25,198.5)
  TOP w0.5: IC23.4 420.7,206.6 ; 418.05,208.45 IC23.1 418.55,208.45
  TOP w1.7: 418.48,210.25 TP41.1
  BOTTOM w0.3: v1(416.25,198.5) v1(416.25,209.5)
AD4: length 505.8
  TOP w0.25: v1(430.8,128.8) 429.2,128.8 428.25,129.75 CN9.17
  TOP w0.3: v1(394,120) 394,27.8 385.7,19.5 290,19.5 284,25.5 187.75,25.5 173.5,39.75 v1(173.5,64.5) ; IC31.3 IC31.4 81.95,79.2 81.75,79 v1(81.75,77.75) 81.75,75.52
  TOP w1.7: 81.75,75.52 TP13.1
  BOTTOM w0.3: v1(394,120) 429.75,120 430.8,121.05 v1(430.8,128.8) ; v1(81.75,77.75) 81.75,75.75 93,64.5 v1(173.5,64.5)
AD5: length 456.3
  TOP w0.25: CN9.18 416.45,129.75 415.1,128.4 414.3,128.4
  TOP w0.3: 124.75,77.52 124.75,78.75 124.85,78.85 IC33.3 IC33.4 ; v1(401.5,128.5) 401.5,26.3 388.7,13.5 287,13.5 281,19.5 148.5,19.5 v1(124.75,43.25) ; 124.75,76.98 v1(124.75,50.5) ; 414.3,128.4 v1(412.9,128.4)
  TOP w1.7: 124.75,77.52 TP14.1 124.75,76.98
  BOTTOM w0.3: v1(401.5,128.5) 412,128.5 412.1,128.4 v1(412.9,128.4) ; v1(124.75,50.5) v1(124.75,43.25)
AD6: length 433.6
  TOP w0.25: CN9.21 430.07,130.75 v1(430.8,130.9)
  TOP w0.3: 181.98,72.25 180,72.25 179.25,71.5 171.95,71.5 171.2,70.75 171.2,39.5 187.2,23.5 283,23.5 289,17.5 386.6,17.5 396.5,27.4 v1(396.5,117.5) ; 182.25,72.52 182.25,75.75 182.6,76.1 IC35.3 IC35.4
  TOP w1.7: 181.98,72.25 TP15.1 182.25,72.52
  BOTTOM w0.3: v1(430.8,130.9) 432.1,130.9 432.75,130.25 432.75,119.5 430.75,117.5 v1(396.5,117.5)
AD7: length 43.4
  TOP w0.25: v1(413.5,130.3) 415.4,130.3 415.85,130.75 CN9.22
  TOP w0.3: v1(406.9,130.3) 406.9,117.35 412.05,112.2 413.05,112.2 ; 415.45,110.3 414.95,110.3 414.5,110.75 414.5,112 414.3,112.2 413.55,112.2
  TOP w0.5: 418.65,111.5 417.45,111.5 416.25,110.3 IC2.4 415.45,110.3 ; 413.05,112.2 IC2.1 413.55,112.2
  TOP w1.7: 418.65,111.5 TP10.1
  BOTTOM w0.3: v1(413.5,130.3) v1(406.9,130.3)
FG: length 235.8
  TOP w1: C13.2 56,312.5 ; C13.2 54,311 ; C13.2 58,311 ; C15.2 25,304 ; C15.2 27,305.5 ; C15.2 28.5,304 ; C18.2 156,312.8 ; C18.2 157.8,311 ; C18.2 154.2,311 ; C14.2 80,312.8 ; C14.2 78.2,311 ; C14.2 81.8,311 ; C16.2 129.8,311 ; C16.2 126.2,311 ; C16.2 128,312.8 ; C17.2 101.8,311 ; C17.2 100,312.8 ; C17.2 98.2,311
  TOP w1.5: TB4.2 13,314.4 ; TB4.2 9,311.4 ; TB4.2 13,308.4 ; TB4.2 17.75,311.4 ; TB4.1 13,305.6 ; TB4.1 17.75,302.6 ; TB4.1 9,302.6
  CONDUCTIVE2 w1: C18.2 156,312.7 ; C18.2 157.7,311 ; C18.2 154.3,311 ; C16.2 128,312.7 ; C16.2 129.7,311 ; C16.2 126.3,311 ; C15.2 25.3,304 ; C15.2 28.7,304 ; C15.2 27,305.7 ; C13.2 54.3,311 ; C13.2 57.7,311 ; C13.2 56,312.7 ; C14.2 80,312.7 ; C14.2 78.3,311 ; C14.2 81.7,311 ; C17.2 98.3,311 ; C17.2 100,312.7 ; C17.2 101.7,311
  CONDUCTIVE2 w1.5: TB4.2 13,314.4 ; TB4.2 8.3,311.4 ; TB4.2 17.75,311.4 ; TB4.2 13,308.4 ; TB4.1 8.3,302.6 ; TB4.1 13,305.6 ; TB4.1 17.75,302.6
  CONDUCTIVE3 w1: C18.2 157.7,311 ; C18.2 154.3,311 ; C18.2 156,312.7 ; C16.2 126.3,311 ; C16.2 129.7,311 ; C16.2 128,312.7 ; C14.2 78.3,311 ; C14.2 80,312.7 ; C14.2 81.7,311 ; C17.2 98.3,311 ; C17.2 101.7,311 ; C17.2 100,312.7 ; C15.2 27,305.7 ; C15.2 28.7,304 ; C15.2 25.3,304 ; C13.2 56,312.7 ; C13.2 54.3,311 ; C13.2 57.7,311
  CONDUCTIVE3 w1.5: TB4.2 13,308.4 ; TB4.2 17.75,311.4 ; TB4.2 13,314.4 ; TB4.2 8.4,311.4 ; TB4.1 8.3,302.6 ; TB4.1 17.75,302.6 ; TB4.1 13,305.6
  BOTTOM w1: C18.2 157.8,311 ; C18.2 156,312.8 ; C18.2 154.2,311 ; C15.2 28.8,304 ; C15.2 27,305.8 ; C15.2 25.2,304 ; C16.2 126.2,311 ; C16.2 128,312.8 ; C16.2 129.8,311 ; C13.2 57.8,311 ; C13.2 54.2,311 ; C13.2 56,312.8 ; C14.2 81.8,311 ; C14.2 80,312.8 ; C14.2 78.2,311 ; C17.2 100,312.8 ; C17.2 98.2,311 ; C17.2 101.8,311
  BOTTOM w1.5: TB4.1 8.3,302.6 ; TB4.1 13,305.6 ; TB4.1 17.75,302.6 ; TB4.2 13,314.4 ; TB4.2 8.3,311.4 ; TB4.2 13,308.4 ; TB4.2 17.75,311.4
GATE_U_A: length 3.6
  BOTTOM w1: Q1.G 352.23,250.15
GATE_U_B: length 3.6
  BOTTOM w1: Q2.G 352.23,226.15
GATE_V_A: length 3.6
  BOTTOM w1: Q3.G 352.23,168.15
GATE_V_B: length 3.6
  BOTTOM w1: Q4.G 352.23,144.15
GATE_W_A: length 3.5
  BOTTOM w1: Q5.G 352.23,86.05
GATE_W_B: length 3.6
  BOTTOM w1: Q6.G 352.23,62.15
IU: length 11.1
  TOP w0.3: 78,91.99 78,93.25 78.14,93.39 78.14,101.95
  TOP w0.6: CT1.7 78.14,101.95
  TOP w0.8: 78,91.99 R23.1
IV: length 10.6
  TOP w0.3: 127.14,101.95 127.14,93.44 R25.1
  TOP w0.6: 127.14,101.95 CT2.7
IW: length 13.4
  TOP w0.3: 182.75,89.99 182.75,98.05 183.63,98.94 183.63,101.95
  TOP w0.6: CT3.7 183.63,101.95
  TOP w0.8: 182.75,89.99 R26.2
SIG193: length 232.3
  TOP w1: 80.16,299 R2.1 78.16,297 ; ZNR3.2 49.25,239.35 ; ZNR3.2 51.25,241.35 ; ZNR3.2 49.25,243.35 ; R8.2 49.66,233 ; R8.2 49.66,237 ; R8.2 51.66,235 ; C14.1 80,299.8 ; C14.1 81.8,301 ; C14.1 78.2,301 ; L1.3 67.05,236.65 ; L1.3 64.8,238.9 ; L1.3 64.8,234.4 ; L1.3 62.55,236.65 ; C10.1 49.75,229.5 ; C10.1 52.25,227 ; C10.1 49.75,224.5 ; C2.2 83.75,291 ; C2.2 86.25,288.5 ; C2.2 86.25,293.5 ; ZNR1.1 76.75,279.35 ; ZNR1.1 74.75,281.35 ; ZNR1.1 74.75,277.6 ; F2.2 49,253.9 ; F2.2 50.9,252 ; F2.2 49,250.1
  CONDUCTIVE2 w1: C10.1 51.02,225.73 ; C10.1 48.48,228.27 ; C10.1 51.02,228.27 ; C10.1 48.48,225.73 ; R8.2 51.07,233.59 ; R8.2 48.25,236.41 ; R8.2 51.07,236.41 ; R8.2 48.25,233.59 ; F2.2 47.73,253.27 ; F2.2 47.73,250.73 ; F2.2 50.27,253.27 ; F2.2 50.27,250.73 ; R2.1 80.16,299 ; R2.1 75.9,299 ; R2.1 78.16,301 ; R2.1 78.16,297 ; C14.1 82.7,301 ; C14.1 80,299.8 ; C14.1 78.3,301 ; C2.2 86.25,292.8 ; C2.2 86.25,289.2 ; C2.2 84,291 ; C2.2 88.05,291 ; ZNR3.2 50.52,240.08 ; ZNR3.2 47.98,240.08 ; ZNR3.2 50.52,242.62 ; ZNR3.2 47.98,242.62 ; ZNR1.1 72.95,279.35 ; ZNR1.1 76.55,279.35 ; ZNR1.1 74.75,277.55 ; ZNR1.1 74.75,281.15
  CONDUCTIVE2 w1.5: L1.3 62.4,236.65 ; L1.3 64.8,234.25 ; L1.3 67.2,236.65 ; L1.3 64.8,239.05
  CONDUCTIVE3 w1: R8.2 51.66,235 ; R8.2 49.66,237 ; R8.2 49.66,233 ; ZNR3.2 49.25,239.55 ; ZNR3.2 49.25,243.15 ; ZNR3.2 51.05,241.35 ; C10.1 49.75,228.8 ; C10.1 49.75,225.2 ; C10.1 51.55,227 ; F2.2 50.8,252 ; F2.2 49,250.2 ; F2.2 49,253.8 ; R2.1 78.16,301 ; R2.1 76.16,299 ; R2.1 78.16,297 ; R2.1 80.16,299 ; 78.3,301 C14.1 81.7,301 ; C2.2 86.25,292.8 ; C2.2 86.25,289.2 ; C2.2 88.05,291 ; C2.2 84.45,291 ; 76.75,279.35 ZNR1.1 74.75,281.96
  CONDUCTIVE3 w1.5: 64.8,234.25 L1.3 62.4,236.65
  BOTTOM w1: R2.1 76.16,299 ; R2.1 78.16,301 ; R2.1 80.16,299 ; R2.1 78.16,297 ; R8.2 51.66,235 ; R8.2 49.66,237 ; R8.2 49.66,233 ; ZNR3.2 51.25,241.35 ; ZNR3.2 49.25,239.35 ; ZNR3.2 49.25,243.35 ; C2.2 86.25,288.5 ; C2.2 86.25,293.5 ; C2.2 88.4,291 ; C2.2 83.75,291 ; F2.2 50.9,252 ; F2.2 49,250.1 ; F2.2 49,253.9 ; 81.8,301 C14.1 78.2,301 ; 52.25,227 C10.1 49.75,229.5 ; 74.75,281.35 ZNR1.1 76.75,279.35
  BOTTOM w1.5: L1.3 62.3,236.65 ; L1.3 64.8,239.15 ; L1.3 64.8,234.15 ; L1.3 67.3,236.65
SOURCE_U: length 54.6
  TOP w0.3: 355.3,206.05 355.3,205.19 ; 355.3,203.95 355.3,204.81 ; 356.35,205 355.49,205
  TOP w0.5: 360.57,210.63 361.06,210.63 361.9,209.8 362.38,209.8 ; 362.5,210.07 v1(362.5,211.91) 360.83,211.91 ; 352.5,207.93 v1(352.5,206.5)
  TOP w0.6: IC4.3 360.57,210.63 ; IC4.4 360.83,211.91
  TOP w0.8: 362.5,210.07 C65.2 362.38,209.8 ; R45.1 352.5,207.93 ; 355.3,204.81 C64.2 ; C64.2 355.3,205.19 ; C64.2 355.49,205
  TOP w1: v1(356,202.2) C63.2 358.25,199.4
  TOP w1.2: PS3.5 366.1,196.59 366.1,198.3
  CONDUCTIVE2 w0.5: 366.3,194.5 366.69,194.89 PS3.5 ; 366.3,197.5 366.69,197.11 PS3.5 ; PS3.5 365.05,196
  CONDUCTIVE2 w1.5: Q2.S 354.53,233.45 ; Q2.S 352.23,235.75 ; Q2.S 352.23,231.15 ; 354.53,257.45 Q1.S 352.23,255.25
  CONDUCTIVE3 w1.5: Q2.S 352.23,235.75 ; Q1.S 352.23,255 ; Q1.S 352.23,259.75 ; Q1.S 349.93,257.45
  BOTTOM w1: 352.23,231 Q2.S 354.35,233.45 ; 354.35,257.45 Q1.S 352.23,255.25
  vias: v1(360.9,205.5) v1(363.25,248.5) v1(363.25,225)
SOURCE_V: length 54.4
  TOP w0.3: 356.35,127 355.49,127 ; 355.3,125.95 355.3,126.81
  TOP w0.5: 360.83,132.91 v1(362.4,132.91) 362.5,131.9 362.5,130.87 ; 352,128.43 v1(352,127) ; 360.57,131.63 360.96,131.63 361.8,130.8 362.28,130.8
  TOP w0.6: IC5.3 360.57,131.63 ; IC5.4 360.83,132.91
  TOP w0.8: 355.3,126.81 C72.2 355.49,127 ; R58.1 352,128.43 ; 362.28,130.8 C73.2 362.5,130.87
  TOP w1: 358.25,119.9 C71.2 v1(356,122)
  TOP w1.2: 366.1,119 366.1,117.59 PS4.5
  CONDUCTIVE2 w0.5: PS4.5 366.69,115.89 366.3,115.5 ; PS4.5 366.69,118.11 366.3,118.5 ; PS4.5 365,117
  CONDUCTIVE2 w1.5: Q4.S 352.23,150 ; Q4.S 352.23,153.75 ; Q4.S 354.53,151.45 ; Q3.S 352.23,177.75 ; Q3.S 354.53,175.45 ; Q3.S 352.23,173.15
  CONDUCTIVE3 w1.5: Q3.S 349.93,175.45 ; Q3.S 352.23,177.75 ; Q3.S 352.23,173.4 ; Q4.S 352.23,153.75
  BOTTOM w1: 354.6,151.45 Q4.S 352.23,149 ; 352.23,173 Q3.S 354.6,175.45
  vias: v1(363.25,167) v1(363.25,143) v1(365.2,126.5)
SOURCE_W: length 56.2
  TOP w0.3: 355.35,44.5 354.49,44.5 ; 354.3,43.45 354.3,44.31
  TOP w0.5: 362,49.08 362,49.5 ; 362,49.5 361.87,49.63 360.33,49.63 ; 362,49.5 v1(362,50.91) 360.33,50.91 ; 351,46.42 v1(351,45.1)
  TOP w0.6: IC6.4 360.33,50.91 ; IC6.3 360.33,49.63
  TOP w0.8: 354.49,44.5 C80.2 354.3,44.31 ; R71.1 351,46.42 ; C81.2 362,49.08
  TOP w1: 358,39.4 C79.2 v1(355,41.3)
  TOP w1.2: PS5.5 366.1,37.09 366.1,38.5
  CONDUCTIVE2 w0.5: PS5.5 365,36.5 ; PS5.5 366.69,35.39 366.3,35 ; PS5.5 366.69,37.61 366.3,38
  CONDUCTIVE2 w1.5: Q5.S 352.23,91.5 ; Q5.S 354.53,93.45 ; Q5.S 351.13,93.45 ; Q5.S 352.23,95.75 ; Q6.S 352.23,67.15 ; Q6.S 352.23,71.75 ; Q6.S 354.53,69.45
  CONDUCTIVE3 w1.5: Q5.S 349.93,93.45 ; Q5.S 352.23,95.75 ; Q5.S 352.23,91.5 ; Q6.S 352.23,71.75
  BOTTOM w1: 354.6,69.45 Q6.S 352.23,67 ; 352.23,91 Q5.S 354.6,93.45
  vias: v1(363.25,85) v1(363.25,61) v1(365.8,44.7)
VDC_M: length 326.1
  TOP w0.3: 396.7,241.19 396.7,242.81 ; 396.7,243.19 v1(396.7,244.7) ; 412,238.81 412,239.6 411.7,239.9 411.7,240.81 ; 396.51,241 395.1,241 394.5,240.4 394.5,237.64 ; 411.51,241 410.1,241 409.5,240.4 409.5,237.64 ; 411.7,241.19 411.7,242.81 ; 411.7,243.19 v1(411.7,244.5) ; 397,238.93 397,239.7 396.7,240 396.7,240.98
  TOP w0.45: R116.1 394.5,237.64 ; R131.1 409.5,237.64
  TOP w0.6: L13.2 412,238.81 ; 397,238.93 L12.2
  TOP w0.8: 396.7,243.19 R110.1 396.7,242.81 ; 411.7,242.81 R125.1 411.7,243.19 ; 411.7,240.81 C109.2 ; C109.2 411.51,241 ; C109.2 411.7,241.19 ; C104.2 396.7,241.19 ; C104.2 396.7,240.98 ; C104.2 396.51,241
  CONDUCTIVE2 w0.3: 413,277 420.6,277 423.9,273.7 423.9,250.3 427.1,247.1 428.6,247.1 429.1,246.6 429.1,244.7 428.9,244.5 v1(411.7,244.5) ; 401.4,274.6 402.2,273.8 402.2,255.3 399.8,252.9 394.5,252.9 394,252.4 394,248.75 394.25,248.5 398.5,248.5 399,248 399,245.25 398.45,244.7 v1(396.7,244.7)
  CONDUCTIVE2 w1.5: C42.1 379.61,275.54 ; C42.1 374.31,275.54 ; C42.1 376.96,272.89 ; C42.1 376.96,278.19 ; C32.2 381.39,302.46 ; C32.2 384.04,299.81 ; C32.2 386.69,302.46 ; C33.2 408.89,302.46 ; C33.2 414.19,302.46 ; C33.2 411.54,299.81 ; Q4.D 341.53,146 ; C43.1 404.46,278.19 ; C43.1 404.46,272.89 ; C43.1 401.81,275.54 ; C43.1 407.11,275.54 ; Q2.D 341.53,228 ; Q6.D 341.53,64
  BOTTOM w1.3: 343.83,148.25 Q4.D 343.83,143.5 ; 343.83,225.75 Q2.D 343.83,230.25 ; 343.83,61.5 Q6.D 343.83,66.5
  BOTTOM w1.5: 317.65,71.75 C45.1 C44.1 317.65,56.25 ; C43.1 407.21,275.54 ; C43.1 404.46,278.29 ; C43.1 401.71,275.54 ; 371.5,287.5 371.5,285.5 ; 317.65,95.75 C31.2 C30.2 317.65,80.25 ; 317.65,220.25 C34.1 C36.1 317.65,235.75 ; C32.2 384.04,299.71 ; C32.2 386.79,302.46 ; C32.2 381.29,302.46 ; C33.2 411.54,299.71 ; C33.2 408.79,302.46 ; C33.2 414.25,302.46 ; 343.8,146 341.4,146 ; 317.65,177.75 C28.2 C29.2 317.65,162.25 ; R15.1 374.35,288.27 ; 343.8,228 341.4,228 ; 317.65,244.25 C27.2 C26.2 317.65,259.75 ; 343.8,64 341.4,64 ; R16.2 374.35,284.73 ; 376.96,278.29 C42.1 379.71,275.54 ; 317.65,138.25 C41.1 C40.1 317.65,153.75
  BOTTOM w1.9: 371.5,285.5 R16.2 ; R15.1 371.5,287.5
  vias: v1(332.5,275) v1(332.5,273) v1(332.5,206.5) v1(332.5,204.5) v1(332.5,193.5) v1(332.5,191.5) v1(332.5,124) v1(332.5,122) v1(332.5,111.5) v1(332.5,109.5) v1(332.5,43) v1(332.5,41) v1(333.5,274) v1(333.5,205.5) v1(333.5,192.5) v1(333.5,123) v1(333.5,110.5) v1(333.5,42) v1(334.5,275) v1(334.5,273) v1(334.5,206.5) v1(334.5,204.5) v1(334.5,193.5) v1(334.5,191.5) v1(334.5,124) v1(334.5,122) v1(334.5,111.5) v1(334.5,109.5) v1(334.5,43) v1(334.5,41) v1(335.5,274) v1(335.5,205.5) v1(335.5,192.5) v1(335.5,123) v1(335.5,110.5) v1(335.5,42) v1(336.5,275) v1(336.5,273) v1(336.5,206.5) v1(336.5,204.5) v1(336.5,193.5) v1(336.5,191.5) v1(336.5,124) v1(336.5,122) v1(336.5,111.5) v1(336.5,109.5) v1(336.5,43) v1(336.5,41)
VDC_N: length 192.5
  TOP w0.3: 429,249.99 v1(429,251.7)
  TOP w0.8: R117.1 429,249.99
  CONDUCTIVE3 w1.5: TB6.2 437,271.4 ; TB6.2 441.7,274.4 ; TB6.2 437,277.4 ; TB6.2 432.25,274.4 ; D8.3 287.77,58.56 290.12,58.56 ; D8.3 290.07,58.55 ; D8.3 287.77,56.21 ; 290.12,222.56 287.77,222.56 D7.3 287.77,220.21 ; C42.2 381.39,268.46 ; C42.2 384.04,271.11 ; C42.2 386.69,268.46 ; C42.2 384.04,265.81 ; D9.1 281.98,151.45 ; D9.1 277.38,151.45 ; D9.1 279.68,153.75 ; D9.1 279.68,149.15 ; D9.3 290.07,140.55 ; D9.3 287.77,140.56 290.12,140.56 ; D9.3 287.77,138.21 ; C43.2 411.54,271.11 ; C43.2 408.89,268.46 ; C43.2 414.19,268.46 ; C43.2 411.54,265.81 ; TB6.1 441.7,265.6 ; TB6.1 432.25,265.6 ; TB6.1 437,268.6 ; TB6.1 437,262.6 ; D8.1 277.38,69.45 ; D8.1 279.68,71.75 ; D8.1 279.68,67.15 ; D8.1 281.98,69.45 ; D7.1 279.68,231.15 ; D7.1 277.38,233.45 ; D7.1 281.98,233.45 ; D7.1 279.68,235.75
  BOTTOM w1.5: D8.1 279.68,71.85 ; D8.1 282.08,69.45 ; D8.1 277.28,69.45 ; D9.3 285.37,140.55 ; D9.3 290.17,140.55 ; D9.3 287.77,138.15 ; D7.1 279.68,235.85 ; D7.1 282.08,233.45 ; D7.1 277.28,233.45 ; D7.3 287.77,220.15 ; D7.3 290.17,222.55 ; D7.3 285.37,222.55 ; D8.3 287.77,56.15 ; D8.3 290.17,58.55 ; D8.3 285.37,58.55 ; D9.1 282.08,151.45 ; D9.1 279.68,153.85 ; D9.1 277.28,151.45 ; 311.35,220.25 C34.2 C36.2 ; 311.35,138.25 C41.2 C40.2 ; 311.35,56.25 C44.2 C45.2 ; C42.2 374.31,268.46 R17.1
VDC_P: length 149.7
  TOP w0.3: 397.5,255.99 v1(397.5,257.3)
  TOP w0.8: R105.1 397.5,255.99
  CONDUCTIVE2 w1.5: TB5.2 441.6,310.4 ; TB5.2 432.25,310.4 ; TB5.2 437,307.4 ; TB5.2 437,313.4 ; TB5.1 437,298.6 ; TB5.1 437,304.6 ; TB5.1 441.7,301.6 ; TB5.1 432.25,301.6 ; C32.1 379.61,309.54 ; C32.1 376.96,312.19 ; C32.1 374.31,309.54 ; C33.1 407.11,309.54 ; C33.1 404.46,312.19 ; C33.1 401.81,309.54
  CONDUCTIVE2 w2.1: D4.2 290.07,252 ; D5.2 290.07,170 ; D6.2 290.07,88
  BOTTOM w1.5: C32.1 379.71,309.54 ; C32.1 374.21,309.54 ; C32.1 376.96,312.29 ; C33.1 404.46,312.29 ; C33.1 401.71,309.54 ; C33.1 407.21,309.54 ; 311.35,259.75 C26.1 C27.1 ; 311.35,95.75 C31.1 C30.1 ; 371.5,304.95 R14.2 368.65,302.73 ; TB5.2 441.5,310.4 ; TB5.2 437,307.4 ; TB5.2 437,313.4 ; TB5.2 432.25,310.4 ; TB5.1 432.25,301.6 ; TB5.1 437,298.6 ; TB5.1 437,304.6 ; TB5.1 441.6,301.6 ; 311.35,177.75 C28.1 C29.1
  BOTTOM w2.3: D5.2 290.17,170 ; D6.2 290.17,88 ; D4.2 290.17,252
VREF: length 97.5
  TOP w0.3: 113.02,71 112,71 111.75,70.75 110.75,70.75 110.55,70.95 109.7,70.95 ; 109.7,75.2 110.35,75.2 110.5,75.05 111.06,75.05 ; 89.95,77.7 91.3,77.7 93.5,75.5 v1(93.5,74) ; IC20.3 127.55,71.45 128,71 v1(128.75,71) ; C50.1 112,75.05 v1(113,75.25) 113,73.25 113.25,73 113.25,71.27 ; 164.38,76.2 163.75,76.2 v1(163,76.25) ; 120.95,74.95 121.75,74.95 121.94,75.03 v1(122.5,75.25)
  TOP w0.5: IC1.5 109.7,75.2 ; IC28.3 89.95,77.7 ; IC10.3 109.7,70.95 ; IC29.3 120.95,74.95 ; IC30.3 164.38,76.2
  TOP w0.8: 111.06,75.05 C50.1
  TOP w1.7: 113.25,71.27 TP11.1 113.02,71
  BOTTOM w0.3: v1(93.5,74) 94,74.5 112.25,74.5 v1(113,75.25) v1(122.5,75.25) 126.75,71 v1(128.75,71) 134,76.25 v1(163,76.25)
VREF_AC_UV: length 29.1
  TOP w0.3: 96.05,87.19 96.05,88.31 ; 109.2,69.05 108.5,69.05 108.25,69.3 108.25,70.5 107.8,70.95 107.3,70.95 ; 102.52,71 105,71 105.05,70.95 106.8,70.95 ; 96.24,87 97,87 99.5,84.5 99.5,73.75 TP36.1
  TOP w0.5: IC10.4 107.3,70.95 ; 109.2,69.05 IC10.1
  TOP w0.8: 96.24,87 C151.2 96.05,87.19 ; 96.05,88.31 R146.1
  TOP w1.7: 102.52,71 TP36.1
VREF_AC_WV: length 36
  TOP w0.3: 129.7,72.05 129.12,72.05 128.75,72.42 128.75,73.75 128.55,73.95 127.8,73.95 ; C153.2 143.25,85.3 v1(143.25,74) ; 130.2,72.05 130.75,72.05 v1(131.75,72) 132.75,71 133.77,71 ; 141.55,87.19 141.55,88.31
  TOP w0.5: 130.2,72.05 IC20.4 129.7,72.05 ; IC20.1 127.8,73.95
  TOP w0.8: C153.2 141.55,87.19 ; 141.55,88.31 R148.1
  TOP w1.7: 133.77,71 TP56.1
  BOTTOM w0.3: v1(143.25,74) 133.75,74 v1(131.75,72)
VREF_IN_U: length 39.1
  TOP w0.3: 76.75,86.24 76.75,87.22 C47.1 76.7,87.83 76.7,88.56 ; R18.1 v1(78.25,86.05) ; 76.86,101.95 76.86,93.55 76.7,93.39 76.7,88.94 ; v1(85.5,79.25) 85.5,77.95 ; 85.5,77.95 85.75,77.7 ; 85.5,77.95 85.5,77.7 ; 85.5,77.7 85.75,77.7 ; 85.5,77.7 85.5,77.5 85.25,77.25 85.25,75.52 ; 85.75,77.7 87.05,77.7 ; 87.55,77.7 88.25,77.7 88.5,77.45 88.5,76.25 88.95,75.8 89.45,75.8
  TOP w0.5: IC28.1 89.45,75.8 ; 87.05,77.7 IC28.4 87.55,77.7
  TOP w0.6: CT1.6 76.86,101.95
  TOP w0.8: 76.7,88.56 R21.2 76.7,88.94 ; 76.75,86.24 R18.1
  TOP w1.7: 85.25,75.52 TP62.1
  BOTTOM w0.3: v1(85.5,79.25) 84.5,79.25 78.25,85.5 v1(78.25,86.05)
VREF_IN_V: length 38.6
  TOP w0.3: 124.7,89.47 124.7,88.47 C54.1 124.75,87.97 124.75,86.99 ; 115.77,75 117.25,75 117.3,74.95 118.05,74.95 ; 120.45,73.05 119.95,73.05 119.5,73.5 119.5,74.7 ; 124.7,89.69 124.7,93.2 125.86,94.36 125.86,101.95 ; 119.25,74.95 118.55,74.95 ; 119.25,74.95 119.5,74.7 ; 119.25,74.95 119.5,75.2 ; 119.5,74.7 119.5,75.2 ; 119.5,75.2 119.5,75.5 123.5,79.5 123.5,86.5 123.8,86.8 124.73,86.8
  TOP w0.5: 118.05,74.95 IC29.4 118.55,74.95 ; IC29.1 120.45,73.05
  TOP w0.6: 125.86,101.95 CT2.6
  TOP w0.8: 124.7,89.69 R28.2 124.7,89.47 ; 124.75,86.99 R30.1 124.73,86.8
  TOP w1.7: 115.77,75 TP63.1
VREF_IN_W: length 49.7
  TOP w0.3: R27.1 181.2,85.58 C55.2 181.25,84.97 181.25,83.99 ; 181.2,86.69 181.2,97.7 182.37,98.86 182.37,101.95 ; TP64.1 180.25,77.5 180.25,83.5 180.55,83.8 R32.1 ; 166.45,75.95 166.45,75.25 166.2,75 164.75,75 164.55,74.8 164.55,74.05 ; 176.48,74 171,74 169.5,72.5 165.05,72.5 164.55,73 164.55,73.55
  TOP w0.5: 164.55,73.55 IC30.4 164.55,74.05 ; 166.45,75.95 IC30.1
  TOP w0.6: CT3.6 182.37,101.95
  TOP w0.8: 181.2,86.69 R27.1 ; 181.25,83.99 R32.1
  TOP w1.7: TP64.1 176.48,74
N01434: length 143.4
  TOP w1: F1.1 21.5,282.9 ; F1.1 21.5,279.6 ; F1.1 19.6,281
  TOP w1.5: TB1.1 17.75,276.6 ; TB1.1 8.6,276.6 ; TB1.1 13,279.6 ; TB1.1 13,273.6 ; TB1.2 13,288.4 ; TB1.2 17.75,285.4 ; TB1.2 8.4,285.4 ; TB1.2 13,282.4
  CONDUCTIVE2 w1: F1.1 21.5,282.8 ; F1.1 21.5,279.3 ; F1.1 19.7,281
  CONDUCTIVE2 w1.5: TB1.2 8.3,285.4 ; TB1.2 17.75,285.4 ; TB1.2 13,288.4 ; TB1.2 13,282.4 ; TB1.1 8.3,276.6 ; TB1.1 13,279.6 ; TB1.1 13,273.6 ; TB1.1 17.75,276.6
  CONDUCTIVE3 w1: F1.1 21.5,279.4 ; F1.1 21.5,282.8 ; F1.1 19.7,281
  CONDUCTIVE3 w1.5: TB1.1 13,273.6 ; TB1.1 8.5,276.6 ; TB1.1 13,279.6 ; TB1.1 17.75,276.6 ; TB1.2 13,288.4 ; TB1.2 13,282.4 ; TB1.2 8.5,285.4 ; TB1.2 17.75,285.4
  BOTTOM w1: F1.1 21.5,279.1 ; F1.1 19.6,281 ; F1.1 21.5,282.9
  BOTTOM w1.5: TB1.2 13,288.4 ; TB1.2 8.3,285.4 ; TB1.2 17.75,285.4 ; TB1.2 13,282.4 ; TB1.1 13,274.2 ; TB1.1 13,279.6 ; TB1.1 8.5,276.6 ; TB1.1 17.75,276.6
N01736: length 157.4
  TOP w1: F2.1 8.1,252 ; F2.1 10,250.1 ; F2.1 10,253.9 ; F2.1 11.9,252
  TOP w1.5: TB2.1 13,223.6 ; TB2.1 8.5,220.6 ; TB2.1 13,217.6 ; TB2.1 17.75,220.6 ; TB2.2 17.75,229.4 ; TB2.2 13,232.4 ; TB2.2 13,226.4 ; TB2.2 8.3,229.4
  CONDUCTIVE2 w1: F2.1 10,253.8 ; F2.1 10,250.2 ; F2.1 8.2,252 ; F2.1 11.8,252
  CONDUCTIVE2 w1.5: TB2.2 TB2.1 ; TB2.2 13,232.4 ; TB2.2 8.4,229.4 ; TB2.2 17.75,229.4 ; TB2.1 8.3,220.6 ; TB2.1 17.75,220.6 ; TB2.1 13,217.6
  CONDUCTIVE3 w1: F2.1 10,253.8 ; F2.1 8.2,252 ; F2.1 10,250.2 ; F2.1 11.8,252
  CONDUCTIVE3 w1.5: TB2.1 13,217.6 ; TB2.1 17.75,220.6 ; TB2.1 8.5,220.6 ; TB2.1 TB2.2 ; TB2.2 8.6,229.4 ; TB2.2 17.75,229.4 ; TB2.2 13,232.4
  BOTTOM w1: F2.1 10,253.9 ; F2.1 11.9,252 ; F2.1 8.1,252 ; F2.1 10,250.1
  BOTTOM w1.5: TB2.1 17.75,220.6 ; TB2.1 8.6,220.6 ; TB2.1 13,223.6 ; TB2.1 13,217.6 ; TB2.2 8.6,229.4 ; TB2.2 13,226.4 ; TB2.2 17.75,229.4 ; TB2.2 13,232.4
N01804: length 148.1
  TOP w1: F3.1 14.34,209.34 ; F3.1 14.34,206.66 ; F3.1 11.66,209.34 ; F3.1 11.66,206.66
  TOP w1.5: TB3.1 17.75,180.6 ; TB3.1 13,183.6 ; TB3.1 13,177.6 ; TB3.1 8.6,180.6 ; TB3.2 13,192.4 ; TB3.2 17.75,189.4 ; TB3.2 13,186.4 ; TB3.2 8.3,189.4
  CONDUCTIVE2 w1: F3.1 14.27,209.27 ; F3.1 11.73,209.27 ; F3.1 14.27,206.73 ; F3.1 11.73,206.73
  CONDUCTIVE2 w1.5: TB3.1 13,177.6 ; TB3.1 TB3.2 ; TB3.1 17.75,180.6 ; TB3.2 17.75,189.4 ; TB3.2 13,192.4
  CONDUCTIVE3 w1: F3.1 14.27,206.73 ; F3.1 11.73,206.73 ; F3.1 11.73,209.27 ; F3.1 14.27,209.27
  CONDUCTIVE3 w1.5: TB3.2 13,192.4 ; TB3.2 8.6,189.4 ; TB3.2 17.75,189.4 ; TB3.2 TB3.1 ; TB3.1 17.75,180.6 ; TB3.1 8.6,180.6 ; TB3.1 13,177.6
  BOTTOM w1: F3.1 14.34,206.66 ; F3.1 14.34,209.34 ; F3.1 11.66,209.34 ; F3.1 11.66,206.66
  BOTTOM w1.5: TB3.2 8.5,189.4 ; TB3.2 13,192.4 ; TB3.2 13,186.4 ; TB3.2 17.75,189.4 ; TB3.1 8.5,180.6 ; TB3.1 13,183.6 ; TB3.1 13,177.6 ; TB3.1 17.75,180.6
